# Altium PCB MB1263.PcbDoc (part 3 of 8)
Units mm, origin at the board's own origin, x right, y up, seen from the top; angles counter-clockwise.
Board outline 86 x 120 mm, 6 copper layers (Top Layer, Signal Layer 1, Signal Layer 2, Signal Layer 3, Signal Layer 4, Bottom Layer), stack 1.556 mm thick; 392 components, 421 nets, 1978 pads, 1444 vias.
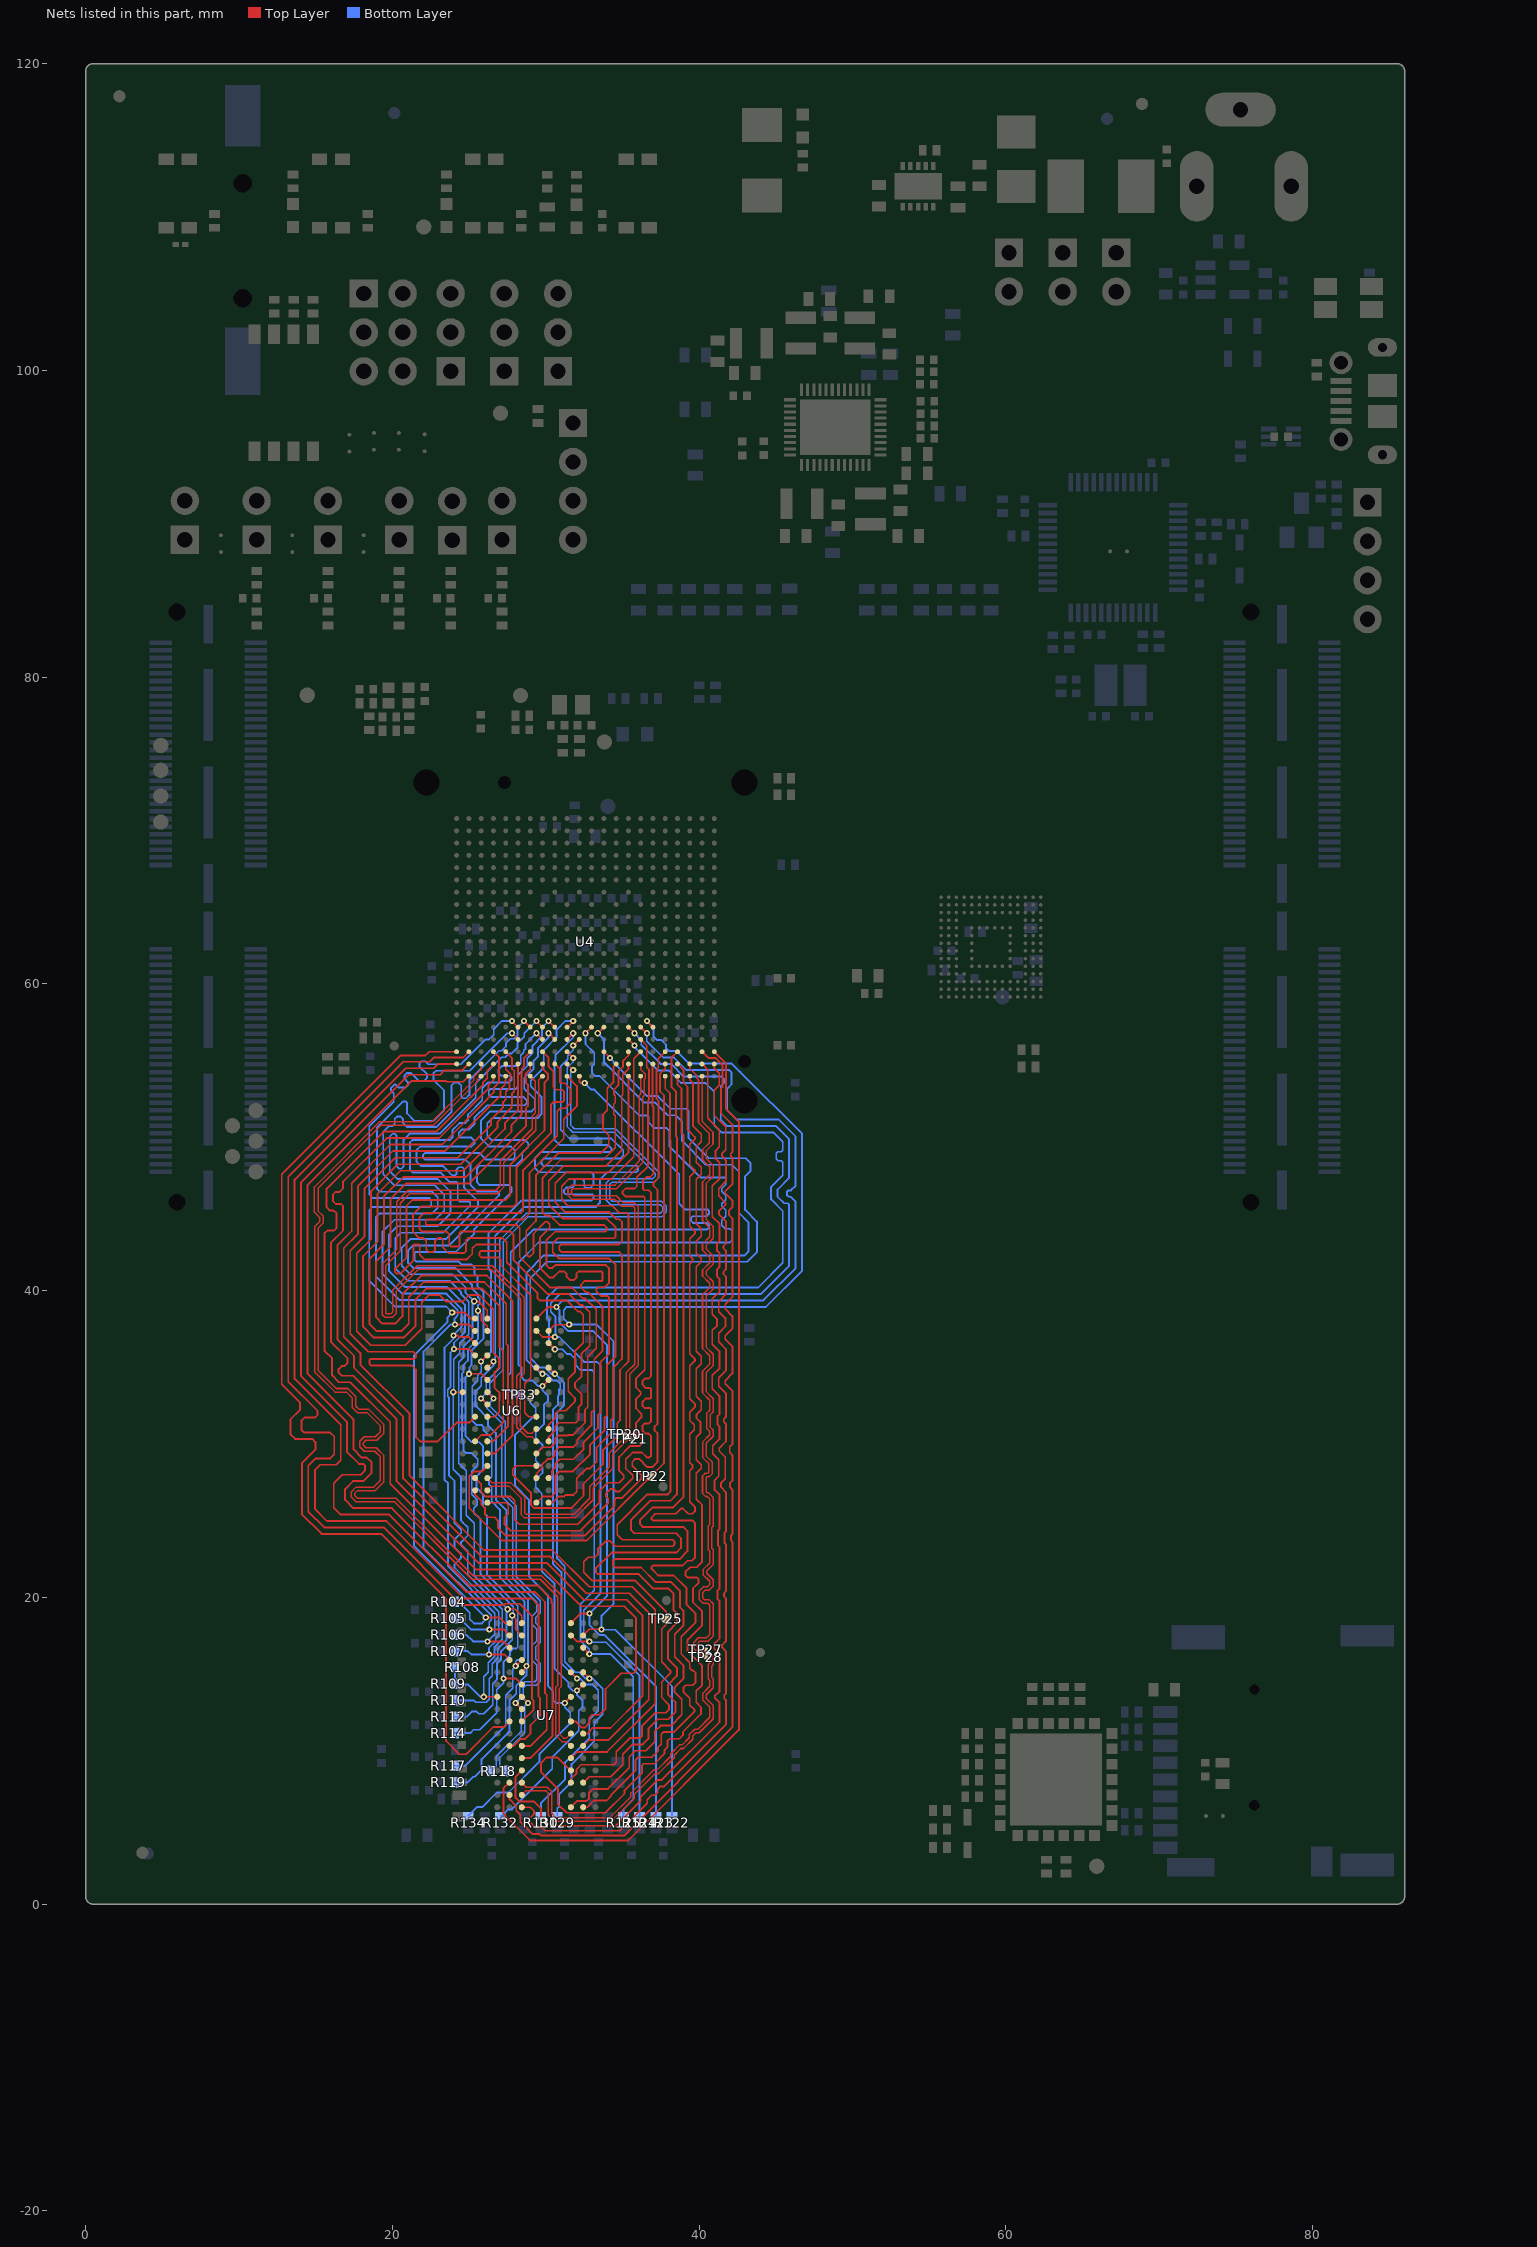
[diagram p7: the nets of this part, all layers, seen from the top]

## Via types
v1: diameter 0.4, hole 0.2, Top Layer to Bottom Layer, tented both sides, 771 vias
v2: diameter 0.6, hole 0.3, Top Layer to Bottom Layer, tented both sides, 670 vias
v3: diameter 0.4, hole 0.2, Top Layer to Bottom Layer, 3 vias

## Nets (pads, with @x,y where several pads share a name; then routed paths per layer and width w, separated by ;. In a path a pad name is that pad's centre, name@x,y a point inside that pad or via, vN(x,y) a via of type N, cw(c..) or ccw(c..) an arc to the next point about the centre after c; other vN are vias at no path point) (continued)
DDR_A4: R106.1 U4.T18 U6.P8 U7.P8 | length 67.9
  Top Layer w0.12: v1(23.99,37.08) 24.27,37.08 24.37,36.98 24.99,36.98 U6.P8@25.39,36.58 ; v1(26.21,17.13) 27.23,17.13 U7.P8@27.64,16.72 ; v1(28.59,57.58) U4.T18@28.99,57.18
  Bottom Layer w0.12: R106.1@24.09,17.57 24.82,17.57 25.26,17.13 v1(26.21,17.13) 26.68,17.6 26.68,18.98 23.63,22.03 23.63,27.44 23.39,27.68 23.39,34.221 23.4,34.231 23.4,36.292 23.99,36.882 v1(23.99,37.08) 23.97,37.08 23.98,37.09 24.5,37.61 24.5,38.828 23.52,39.807 20.653,39.807 19.35,41.11 19.35,43.83 20.14,44.62 22.778,44.62 23.38,45.222 23.38,46.258 22.768,46.87 20.12,46.87 19.41,47.58 19.41,50.37 19.76,50.72 19.98,50.72 20.154,50.894 20.154,51.196 20.309,51.351 20.535,51.351 20.69,51.196 20.69,50.95 20.98,50.66 22.874,50.66 23.845,51.631 23.845,53.375 24.03,53.56 24.31,53.56 24.49,53.38 24.49,52.64 24.59,52.54 24.802,52.54 25.02,52.758 25.02,53.707 26.952,55.638 27.128,55.638 27.41,55.92 27.41,56.142 27.688,56.42 27.939,56.42 28.15,56.631 28.15,57.14 v1(28.59,57.58)
DDR_A5: R125.1 U4.H19 U6.P2 U7.P2 | length 79.3
  Top Layer w0.12: U6.P2@30.19,36.58 v1(30.59,36.18) ; U7.P2@32.44,16.72 v1(32.84,16.32) ; U4.H19@35.39,56.38 v1(35.79,55.98)
  Bottom Layer w0.12: R125.1@35.07,5.77 35.07,6.19 35.71,6.83 35.71,14.82 34.21,16.32 v1(32.84,16.32) 32.84,16.611 32.26,17.191 32.26,19.56 32.46,19.76 33.16,20.46 33.16,34.67 33.005,34.825 32.265,34.825 31.93,35.16 31.93,35.55 31.615,35.865 31.395,35.865 31.08,36.18 v1(30.59,36.18) 30.208,36.562 30.208,38.136 30.083,38.261 30.083,39.536 30.747,40.2 43.838,40.2 45.45,41.812 45.45,45.194 44.69,45.954 44.69,46.763 45.45,47.523 45.45,48.37 45.35,48.47 45.17,48.47 45.03,48.61 45.03,48.96 45.13,49.06 45.36,49.06 45.45,49.15 45.45,49.702 44.832,50.32 41.45,50.32 40.99,50.78 40.99,52.961 40.411,53.54 38.828,53.54 38.008,54.36 37.3,54.36 35.835,55.825 v1@35.835,55.834
DDR_A6: R105.1 U4.U19 U6.R8 U7.R8 | length 68.3
  Top Layer w0.12: v1(24.09,37.8) 24.97,37.8 U6.R8@25.39,37.38 ; U6.R8@25.44,37.38 U6.R8@25.44,37.393 ; v1(26.32,17.91) 27.25,17.91 U7.R8@27.64,17.52 ; v1(27.79,56.78) U4.U19@28.19,56.38
  Bottom Layer w0.12: v1@24.054,37.805 24.054,38.18 24.26,38.386 24.26,38.728 23.601,39.387 20.479,39.387 18.93,40.936 18.93,44.791 19.179,45.04 22.604,45.04 22.96,45.396 22.96,46.084 22.594,46.45 19.19,46.45 18.99,46.65 18.99,50.626 20.69,52.326 20.884,52.326 20.96,52.25 20.96,51.55 21.43,51.08 22.7,51.08 23.37,51.75 23.37,53.05 22.68,53.74 22.68,54.17 22.85,54.34 25.059,54.34 27.499,56.78 v1(27.79,56.78) ; R105.1@24.09,18.64 24.38,18.64 25.11,17.91 v1(26.32,17.91) 26.32,18.401 26.45,18.531 26.45,18.829 22.03,23.249 22.03,36.03 23.8,37.8 v1(24.09,37.8)
DDR_A7: R122.1 U4.F18 U6.R2 U7.R2 | length 80.7
  Top Layer w0.12: U6.R2@30.19,37.38 30.59,37.78 v1@31.509,37.78 ; U7.R2@32.44,17.52 32.84,17.92 v1(33.64,17.92) ; v1(36.59,57.58) U4.F18@36.99,57.18
  Bottom Layer w0.12: v1(36.59,57.58) 37.03,57.14 37.03,56.56 37.24,56.35 37.529,56.35 37.83,56.049 37.83,55.831 38.041,55.62 38.53,55.62 39.35,54.8 42.116,54.8 42.668,54.248 42.686,54.248 46.71,50.224 46.71,41.29 44.36,38.94 31.381,38.94 31.17,38.729 31.17,38.16 v1(31.53,37.8) 33.304,37.8 34.42,36.684 34.42,19.59 33.64,18.81 v1(33.64,17.92) 33.67,17.89 34.539,17.89 38.23,14.199 R122.1@38.23,5.77
DDR_A8: R104.1 U4.U18 U6.T8 U7.T8 | length 69.6
  Top Layer w0.12: v1(23.9,38.57) 24.724,38.57 25.114,38.18 U6.T8@25.39,38.18 ; v1@26.18,18.68 27,18.68 27.36,18.32 U7.T8@27.64,18.32 ; v1(27.79,57.58) U4.U18@28.19,57.18
  Bottom Layer w0.12: R104.1@24.09,19.72 24.33,19.72 25.05,19 25.05,18.581 25.321,18.31 25.84,18.31 26.09,18.56 v1(26.09,18.68) 21.42,23.35 21.42,35.79 23.6,37.97 23.6,38.27 v1(23.9,38.57) 23.503,38.967 20.16,38.967 18.49,40.637 18.49,45.26 18.69,45.46 22.43,45.46 22.54,45.57 22.54,45.91 22.42,46.03 18.73,46.03 18.49,46.27 18.49,50.72 20.09,52.32 20.09,52.86 19.915,53.035 19.915,53.215 20.13,53.43 20.22,53.43 20.415,53.235 20.84,53.235 21.01,53.405 21.01,53.6 20.8,53.81 20.8,54.03 20.97,54.2 21.21,54.2 21.72,53.69 22.07,53.69 22.26,53.88 22.26,54.1 21.76,54.6 21.76,54.81 21.91,54.96 22.15,54.96 22.35,54.76 24.461,54.76 26.081,56.38 26.299,56.38 26.615,56.696 26.615,57.055 27.14,57.58 v1(27.79,57.58)
DDR_A9: R124.1 U4.H18 U6.R3 U7.R3 | length 81.9
  Top Layer w0.12: U6.R3@29.39,37.38 29.79,36.98 v1(30.59,36.98) ; U7.R3@31.64,17.52 32.04,17.12 v1(32.84,17.12) ; U4.H18@35.39,57.18 v1(35.79,56.78)
  Bottom Layer w0.12: v1(30.59,36.98) 30.87,36.98 32.5,35.35 33.35,35.35 33.58,35.12 33.58,20.27 32.48,19.17 32.48,17.48 v1(32.84,17.12) 32.88,17.08 33.929,17.08 36.12,14.889 R124.1@36.12,5.77 ; v1@30.633,37 30.633,38.325 30.323,38.635 30.323,39.182 30.921,39.78 44.012,39.78 45.87,41.638 45.87,45.61 45.78,45.7 45.538,45.7 45.11,46.128 45.11,46.589 45.87,47.349 45.87,49.876 45.006,50.74 41.81,50.74 41.41,51.14 41.41,53.344 41.63,53.564 41.63,53.79 41.46,53.96 39.002,53.96 38.182,54.78 37.487,54.78 36.23,56.033 36.23,56.34 v1(35.79,56.78)
DDR_A10: R114.1 U4.N18 U6.L7 U7.L7 | length 75
  Top Layer w0.12: v1(24.99,34.58) 25.79,34.58 U6.L7@26.19,34.18 ; v1(27.24,14.72) 28.04,14.72 U7.L7@28.44,14.32 ; U4.N18@31.39,57.18 v1(31.79,57.58)
  Bottom Layer w0.12: R114.1@24.09,11.15 25.071,11.15 25.291,11.37 25.69,11.37 26.81,12.49 26.81,13.98 27.24,14.41 v1(27.24,14.72) 27.24,15.788 27.68,16.228 27.68,16.469 27.891,16.68 28.089,16.68 28.177,16.768 28.177,19.463 26.174,21.466 26.174,25.32 26.04,25.454 26.04,25.819 25.9,25.959 25.9,26.74 25.49,27.15 25.49,27.91 25.9,28.32 25.9,29.89 25.67,30.12 25.17,30.12 24.77,30.52 24.77,34.36 v1(24.99,34.58) ; v1@25.033,34.58 25.033,35.01 25.153,35.13 25.153,36.093 25.95,36.89 25.95,39.892 25.549,40.293 25.549,40.891 25.35,41.09 25.35,41.53 25.16,41.72 24.48,41.72 24.293,41.907 21.8,41.907 21.797,41.91 21.52,41.91 21.45,41.98 21.45,42.46 21.51,42.52 24.146,42.52 25.333,43.707 25.333,43.993 27.78,46.44 27.78,46.72 27.62,46.88 25.71,46.88 25.53,47.06 25.53,47.078 25.52,47.088 25.52,47.98 25.68,48.14 28.04,48.14 28.47,48.57 28.47,49.002 28.86,49.392 28.86,49.62 28.66,49.82 26.48,49.82 26.19,50.11 26.19,50.914 26.526,51.25 29.466,51.25 29.72,51.504 29.72,52.64 29.02,53.34 29.02,53.69 29.865,54.535 29.865,55.681 30.69,56.506 30.69,56.989 31.281,57.58 v1(31.79,57.58)
DDR_A11: R112.1 U4.P19 U6.R7 U7.R7 | length 77.4
  Top Layer w0.12: v1@25.51,38.69 v1@25.514,38.69 ; v1(25.58,38.69) 25.81,38.46 25.81,38.051 26.19,37.671 U6.R7@26.19,37.38 ; v1(27.817,18.82) 28.06,18.577 28.06,17.9 U7.R7@28.44,17.52 ; v1(30.19,56.78) U4.P19@30.59,56.38
  Bottom Layer w0.12: R112.1@24.09,12.22 24.861,12.22 25.211,12.57 25.469,12.57 25.619,12.42 25.969,12.42 26.54,12.991 26.54,14.36 26.816,14.636 26.816,15.674 27.09,15.949 27.09,16.5 27.817,17.227 v1(27.817,18.82) 27.83,18.82 27.88,18.87 27.88,19.379 25.75,21.509 25.75,25.09 25.31,25.53 25.31,25.82 25.53,26.04 25.53,26.37 25.18,26.72 25.18,28.22 25.57,28.61 25.57,29.01 25.17,29.41 24.81,29.41 24.63,29.59 24.63,30.203 24.55,30.283 24.55,34.61 24.63,34.69 24.63,35.15 24.933,35.453 24.933,36.184 25.58,36.831 v1(25.58,38.69) 25.58,39.041 25.7,39.161 25.7,39.459 25.58,39.579 25.58,39.753 25.189,40.143 25.189,40.393 24.095,41.487 21.349,41.487 21.03,41.806 21.03,42.634 21.336,42.94 23.686,42.94 26.95,46.204 26.95,46.36 26.85,46.46 25.536,46.46 25.11,46.886 25.11,46.904 25.1,46.914 25.1,48.2 24.75,48.55 22.12,48.55 21.99,48.68 22,48.69 22,48.85 22.13,48.98 25.66,48.98 26.08,48.56 27.866,48.56 27.98,48.674 27.98,49.15 27.73,49.4 26.306,49.4 25.77,49.936 25.77,51.088 26.352,51.67 29.05,51.67 29.3,51.92 29.3,52.466 28.6,53.166 28.6,53.864 29.21,54.474 29.21,54.986 29.505,55.281 29.505,55.831 30.19,56.516 v1(30.19,56.78)
DDR_A12: R117.1 U4.N19 U6.N7 U7.N7 | length 76.3
  Top Layer w0.12: v1(25.79,35.38) U6.N7@26.19,35.78 ; v1(28.04,15.52) U7.N7@28.44,15.92 ; U4.N19@31.39,56.38 v1(31.79,56.78)
  Bottom Layer w0.12: R117.1@24.09,9.02 24.75,9.02 27.39,11.66 27.39,13.61 27.85,14.07 27.85,15.33 v1(28.04,15.52) 28.04,15.83 28.13,15.92 28.44,15.92 28.617,16.097 28.617,19.713 27.014,21.316 27.014,25.729 26.48,26.263 26.48,27.2 26.29,27.39 26.29,27.69 26.48,27.88 26.48,30.36 25.95,30.89 25.95,31.12 25.84,31.23 25.5,31.23 25.21,31.52 25.21,33.77 25.57,34.13 25.57,34.479 25.79,34.699 v1(25.79,35.38) 26.44,36.03 26.44,41.23 26.269,41.401 26.269,43.741 28.398,45.87 32.98,45.87 33.11,46 33.11,46.2 33.02,46.29 31.29,46.29 31.19,46.39 31.19,46.56 31.36,46.73 31.745,46.73 31.87,46.855 31.87,47.17 32,47.3 32.35,47.3 32.51,47.14 32.51,46.8 32.6,46.71 32.93,46.71 33.11,46.89 33.11,47.58 32.97,47.72 29.56,47.72 29.31,47.97 29.31,48.654 29.686,49.03 34.17,49.03 34.29,49.15 34.29,49.26 34.05,49.5 30.9,49.5 30.56,49.84 30.56,54.961 30.63,55.031 30.63,55.345 31.79,56.505 v1(31.79,56.78)
DDR_A13: R123.1 U4.G18 U6.T3 U7.T3 | length 82.1
  Top Layer w0.12: U6.T3@29.39,38.18 30.15,38.94 v1(30.7,38.94) ; U7.T3@31.64,18.32 32.28,18.96 v1(32.86,18.96) ; U4.G18@36.19,57.18 v1(36.59,56.78)
  Bottom Layer w0.12: v1(36.59,56.78) 36.59,56.271 37.661,55.2 38.356,55.2 39.176,54.38 41.95,54.38 42.1,54.23 42.1,53.44 41.83,53.17 41.83,51.77 42.44,51.16 45.18,51.16 46.29,50.05 46.29,46.85 45.98,46.54 45.818,46.54 45.74,46.462 45.74,46.21 45.83,46.12 45.97,46.12 46.29,45.8 46.29,41.464 44.186,39.36 31.12,39.36 v1(30.7,38.94) 30.89,38.75 30.89,37.931 31.446,37.375 33.056,37.375 34,36.431 34,20.1 v1(32.86,18.96) 32.86,18.191 33.491,17.56 33.82,17.56 37.19,14.19 R123.1@37.19,5.77
DDR_A14: R110.1 U4.P18 U6.T7 U7.T7 | length 76.2
  Top Layer w0.12: v1(25.34,39.31) 25.6,39.31 26.19,38.72 U6.T7@26.19,38.18 ; v1(27.52,19.23) 28.01,19.23 28.44,18.8 U7.T7@28.44,18.32 ; v1(30.19,57.58) U4.P18@30.59,57.18
  Bottom Layer w0.12: R110.1@24.09,13.29 25.3,13.29 25.43,13.16 26.109,13.16 26.32,13.371 26.32,14.69 26.515,14.885 26.515,15.685 26.87,16.04 26.87,16.659 27.45,17.239 27.45,19.16 v1(27.52,19.23) 25.334,21.416 25.334,24.836 24.82,25.35 24.82,28.259 24.33,28.749 24.33,35.332 24.63,35.632 24.63,36.34 25.22,36.93 25.22,39.19 v1@25.337,39.308 ; v1(25.34,39.31) v1@25.337,39.308 ; v1(30.19,57.58) 29.75,57.14 29.75,56.585 29.145,55.98 29.145,55.515 28.79,55.16 28.79,54.648 28.18,54.038 28.18,53.3 28.02,53.14 26.39,53.14 26.28,53.03 26.28,52.78 26.43,52.63 28.542,52.63 28.76,52.412 28.76,52.22 28.63,52.09 26.178,52.09 25.35,51.262 25.35,50.86 25,50.51 24.554,50.51 24.33,50.286 24.33,50.058 24.41,49.978 25.152,49.978 25.35,49.78 25.35,49.59 25.16,49.4 21.82,49.4 21.57,49.15 21.57,48.42 21.86,48.13 23.29,48.13 23.92,47.5 24.06,47.5 24.19,47.63 24.19,47.91 24.33,48.05 24.56,48.05 24.68,47.93 24.68,46.722 25.59,45.812 25.59,45.458 23.492,43.36 21.162,43.36 20.61,42.808 20.61,41.632 21.175,41.067 23.921,41.067 24.769,40.219 24.769,39.876 v1@25.337,39.308
DDR_A15: R119.1 U4.M19 U6.M7 U7.M7 | length 76.7
  Top Layer w0.12: U6.M7@26.19,34.98 v1(26.59,35.38) ; U7.M7@28.44,15.12 28.74,15.42 v1(28.74,15.52) ; v1(31.79,55.98) U4.M19@32.19,56.38
  Bottom Layer w0.12: R119.1@24.09,7.94 24.911,7.94 25.281,8.31 25.369,8.31 25.82,8.761 25.82,9.46 27.64,11.28 27.64,13.29 28.08,13.73 28.08,14.252 28.74,14.912 v1(28.74,15.52) 28.837,15.617 28.837,19.863 27.434,21.266 27.434,25.691 26.75,26.375 26.75,30.711 26.23,31.231 26.23,31.69 25.43,32.49 25.43,33.43 25.79,33.79 25.79,34.31 26.59,35.11 v1(26.59,35.38) 26.705,35.495 26.705,43.583 28.572,45.45 33.26,45.45 33.53,45.72 33.53,47.23 34.02,47.72 35.91,47.72 36.01,47.82 36.01,48.05 35.92,48.14 29.85,48.14 29.73,48.26 29.73,48.48 29.86,48.61 34.85,48.61 35.05,48.81 35.05,49.149 34.279,49.92 31.55,49.92 30.98,50.49 30.98,54.645 31.43,55.095 31.43,55.329 31.79,55.689 v1(31.79,55.98)
DDR_BA0: R129.1 U4.K20 U6.M2 U7.M2 | length 75.9
  Top Layer w0.12: U6.M2@30.19,34.98 v1(30.59,34.58) ; U7.M2@32.44,15.12 v1(32.84,14.72) ; U4.K20@33.79,55.58 v1(34.19,55.18)
  Bottom Layer w0.12: R129.1@30.75,5.77 30.75,6.24 30.87,6.36 30.87,7.166 31.685,7.981 31.685,9.135 33.16,10.61 33.16,11.83 33.72,12.39 33.72,14.04 33.04,14.72 v1(32.84,14.72) 32.59,14.72 32.19,15.12 31.931,15.12 31.24,15.811 31.24,22.04 30.74,22.54 30.74,32.063 31.18,32.503 31.18,34.01 30.61,34.58 v1(30.59,34.58) 30.351,34.58 29.941,34.99 29.62,34.99 28.99,35.62 28.99,40.819 30.051,41.88 43.142,41.88 43.77,42.508 43.77,44.498 43,45.268 43,47.449 43.34,47.789 43.34,48.33 43.04,48.63 40.618,48.63 39.31,49.938 39.31,51.706 39.156,51.86 38.132,51.86 37.312,52.68 36.604,52.68 34.42,54.864 34.42,54.94 34.185,55.175 v1@34.18,55.18
DDR_BA1: R107.1 U4.R18 U6.N8 U7.N8 | length 70.2
  Top Layer w0.12: v1@24.029,36.2 24.97,36.2 U6.N8@25.39,35.78 ; v1(26.29,16.28) 27.28,16.28 U7.N8@27.64,15.92 ; v1(29.39,57.58) U4.R18@29.79,57.18
  Bottom Layer w0.12: 24.064,23.792 24.486,24.214 24.486,24.4 24.05,24.836 24.05,27.61 23.689,27.971 23.689,33.041 23.61,33.12 23.61,33.529 23.78,33.699 23.78,35.96 v1(24.02,36.2) 24.02,36.601 24.74,37.321 24.74,38.927 24.74,39.06 23.573,40.227 20.827,40.227 19.77,41.284 19.77,43.654 20.316,44.2 22.952,44.2 23.8,45.048 23.8,46.432 22.942,47.29 20.32,47.29 19.83,47.78 19.83,50.05 20.01,50.23 20.15,50.23 20.28,50.1 20.28,48.11 20.44,47.95 20.585,47.95 20.73,48.095 20.73,49.85 21.12,50.24 23.096,50.24 25.44,52.584 25.44,53.533 27.126,55.218 27.362,55.218 27.609,55.465 27.785,55.465 28.15,55.831 28.15,56.122 28.594,56.565 28.594,56.784 v1(29.39,57.58) ; 24.068,23.788 24.05,23.77 24.05,23.28 24.47,22.86 24.47,22.566 24.05,22.146 24.05,21.95 26.94,19.06 26.94,17.549 26.74,17.349 26.74,17.151 26.29,16.701 v1(26.29,16.28) 25.14,16.28 24.92,16.5 R107.1@24.09,16.5
DDR_BA2: R130.1 U4.K18 U6.M3 U7.M3 | length 77.1
  Top Layer w0.12: U6.M3@29.39,34.98 v1@29.77,34.6 ; U7.M3@31.64,15.12 v1(32.04,14.72) ; v1(33.39,56.78) U4.K18@33.79,57.18
  Bottom Layer w0.12: R130.1@29.68,5.77 29.68,6.57 31.265,8.155 31.265,9.255 32.84,10.83 32.84,12.02 33.42,12.6 33.42,13.94 33.03,14.33 32.62,14.33 32.23,14.72 v1(32.04,14.72) 32.02,14.72 31.02,15.72 31.02,21.65 30.467,22.203 30.467,32.243 30.63,32.405 ; 30.63,32.406 30.79,32.566 30.79,33.117 30.86,33.187 ; 30.87,33.187 30.87,33.551 30.95,33.631 30.95,33.929 30.739,34.14 30.48,34.14 30.04,34.58 v1(29.79,34.58) 29.719,34.58 29.354,34.944 29.276,34.944 28.748,35.472 28.748,41.17 29.877,42.3 42.968,42.3 43.21,42.542 43.21,44.464 42.58,45.094 42.58,47.77 42.14,48.21 40.444,48.21 38.89,49.764 38.89,51.02 38.47,51.44 37.958,51.44 37.138,52.26 36.43,52.26 33.835,54.855 ; v1(33.39,56.78) 33.79,56.38 33.79,54.9 34.08,54.61
DDR_CASN: R134.1 TP33.1 U4.M22 U6.K3 U7.K3 | length 75.4
  Top Layer w0.12: v1(28.99,32.98) U6.K3@29.39,33.38 ; v1(31.24,13.12) U7.K3@31.64,13.52 ; U4.M22@32.19,53.98 32.19,53.62 32.28,53.53 v1(32.54,53.53)
  Bottom Layer w0.12: R134.1@24.94,5.77 25.5,6.33 25.86,6.33 26.81,7.28 27.57,7.28 29.585,9.295 29.585,9.775 29.84,10.03 31.6,11.79 31.6,12.469 31.24,12.829 v1(31.24,13.12) 30.64,13.12 30.47,13.29 30.47,13.9 30.14,14.23 30.14,20.14 28.904,21.376 28.904,26.363 28,27.267 28,30.596 29.35,31.946 29.35,32.329 28.99,32.689 v1(28.99,32.98) 28.27,32.98 TP33.1@28.179,32.98 ; TP33.1@28.27,33.22 28.27,33.071 TP33.1@28.179,32.98 ; v1(32.54,53.53) 32.962,53.108 33.17,53.108 38.7,47.578 38.7,45.656 39.056,45.3 40.55,45.3 40.64,45.21 40.64,45 40.49,44.85 39.59,44.85 39.46,44.72 39.46,44.57 39.61,44.42 40.51,44.42 40.64,44.29 40.64,44.11 40.51,43.98 29.181,43.98 27.719,42.518 27.719,34.653 27.533,34.466 27.533,33.627 28.105,33.055 TP33.1@28.179,32.98
DDR_CKE: R108.2 R109.1 U4.R19 U6.K9 U7.K9 | length 69.4
  Top Layer w0.12: v1(23.97,33.38) U6.K9@24.59,33.38 ; v1(25.96,13.52) U7.K9@26.84,13.52 ; v1(29.39,56.78) U4.R19@29.79,56.38
  Bottom Layer w0.12: R108.2@24.09,15.44 R109.1@24.09,14.37 24.14,14.32 24.935,14.32 25.735,13.52 v1(25.96,13.52) 25.96,14.82 26.25,15.11 26.25,15.73 26.65,16.131 26.65,16.75 27.16,17.26 27.16,19.214 24.91,21.464 24.91,23.014 24.484,23.44 24.484,23.61 24.91,24.036 24.91,24.574 24.604,24.88 24.6,24.88 24.48,25 24.48,27.84 23.97,28.35 v1(23.97,33.38) 24,33.41 24,35.54 24.389,35.929 24.389,36.569 24.98,37.16 24.98,38.939 ; 24.98,38.78 24.98,39.289 24.469,39.8 24.469,39.925 23.747,40.647 21.001,40.647 20.19,41.458 20.19,43.41 20.56,43.78 23.3,43.78 25.073,45.553 25.073,45.735 24.992,45.816 24.384,45.816 24.26,45.94 24.26,47.01 24.19,47.08 23.746,47.08 23.116,47.71 21.32,47.71 21.15,47.88 21.15,49.66 21.31,49.82 23.74,49.82 23.91,49.99 23.91,50.46 24.38,50.93 24.76,50.93 24.93,51.1 24.93,51.48 25.86,52.41 25.86,53.204 26.216,53.56 27.6,53.56 27.76,53.72 27.76,53.92 27.67,54.01 27.11,54.01 26.9,54.22 26.9,54.399 27.152,54.651 28.199,54.651 28.37,54.822 28.37,55.334 28.57,55.534 28.57,55.66 28.69,55.78 28.69,56.08 v1(29.39,56.78)
DDR_CLK_N: R118.2 U4.N21 U6.K7 U7.K7 | length 71.6
  Top Layer w0.1: U6.K7@26.19,33.38 v1(26.59,32.98) ; U7.K7@28.44,13.52 v1(28.84,13.12) ; U4.N21@31.39,54.78 v1(31.79,54.38)
  Bottom Layer w0.1: v1(26.59,32.98) 26.59,32.93 26.35,32.69 26.35,32.475 27.37,31.455 27.37,26.66 28.074,25.956 28.074,21.341 29.64,19.775 29.64,18.985 29.36,18.705 29.36,18.32 29.64,18.04 29.64,17.065 29.34,16.765 29.34,15.995 29.65,15.685 29.65,14.54 29.38,14.27 28.72,14.27 28.54,14.09 28.54,13.42 v1(28.84,13.12) 28.62,12.9 28.62,11.165 27.01,9.555 27.01,9.01 R118.2@27.34,8.68 ; v1@26.633,33 26.621,33.011 26.35,33.283 26.35,33.965 27.24,34.855 27.24,43.213 28.837,44.81 37.555,44.81 37.87,45.125 37.87,45.515 37.555,45.83 34.33,45.83 34.17,45.99 34.17,46.93 34.32,47.08 37.075,47.08 37.38,47.385 37.38,47.724 34.544,50.56 31.86,50.56 31.62,50.8 31.62,54.21 v1(31.79,54.38)
DDR_CLK_P: R118.1 U4.N20 U6.J7 U7.J7 | length 72.5
  Top Layer w0.1: v1(25.79,32.98) U6.J7@26.19,32.58 ; v1(28.04,13.12) U7.J7@28.44,12.72 ; U4.N20@31.39,55.58 v1(31.79,55.18)
  Bottom Layer w0.1: v1(25.79,32.98) 26.12,32.65 26.12,32.38 27.14,31.36 27.14,26.565 27.844,25.861 27.844,21.246 29.41,19.68 29.41,19.08 29.13,18.8 29.13,18.225 29.41,17.945 29.41,17.16 29.11,16.86 29.11,15.9 29.42,15.59 29.42,14.635 29.285,14.5 28.625,14.5 28.31,14.185 28.31,13.39 v1(28.04,13.12) 28.39,12.77 28.39,11.26 26.78,9.65 26.78,9.02 R118.1@26.44,8.68 ; v1@25.833,33.025 26.12,33.313 26.12,34.06 27.01,34.95 27.01,43.308 28.742,45.04 37.46,45.04 37.64,45.22 37.64,45.42 37.46,45.6 34.235,45.6 33.94,45.895 33.94,47.025 34.225,47.31 36.98,47.31 37.15,47.48 37.15,47.629 34.449,50.33 31.765,50.33 31.39,50.705 31.39,54.517 31.78,54.907 31.78,55.17 v1(31.79,55.18)
DDR_CSN: R132.1 U4.L18 U6.L2 U7.L2 | length 78.7
  Top Layer w0.12: v1(29.79,33.78) U6.L2@30.19,34.18 ; v1(32.04,13.92) U7.L2@32.44,14.32 ; v1(32.59,56.78) U4.L18@32.99,57.18
  Bottom Layer w0.12: R132.1@27.04,5.77 27.15,5.77 27.56,6.18 27.79,6.18 30.425,8.815 30.425,9.565 32.155,11.295 32.155,12.605 32.4,12.85 32.4,13.269 32.04,13.629 v1(32.04,13.92) 31.749,13.92 31.47,14.2 31.47,14.47 30.58,15.36 30.58,20.88 29.744,21.716 29.744,26.776 29.35,27.17 29.35,27.68 29.78,28.11 29.78,28.49 29.35,28.92 29.35,29.346 29.78,29.776 29.78,29.96 29.35,30.39 29.35,30.758 29.884,31.292 29.884,32.565 30.15,32.831 30.15,33.129 30.003,33.276 29.79,33.489 v1(29.79,33.78) 29.499,33.78 29.139,34.14 28.64,34.14 28.426,34.354 28.426,34.966 28.219,35.174 28.219,41.83 29.529,43.14 42,43.14 42.161,43.301 42.161,43.889 42.01,44.04 41.71,44.04 41.48,44.27 41.48,44.58 41.74,44.84 41.74,45.26 41.48,45.52 41.48,45.67 41.74,45.93 41.74,46.22 41.48,46.48 41.48,46.66 41.74,46.92 41.74,47.28 41.65,47.37 40.096,47.37 38.05,49.416 38.05,50.43 37.88,50.6 37.066,50.6 36.7,50.966 36.7,51.34 36.62,51.42 36.082,51.42 33.507,53.995 33.216,53.995 33.005,54.206 33.005,54.605 33.16,54.76 33.16,55.51 32.59,56.08 v1(32.59,56.78)
DDR_DQ0: TP22.1 U4.E21 U6.D7 | length 45.5
  Top Layer w0.12: U6.D7@26.19,28.58 26.19,28.557 25.834,28.202 25.303,28.202 25.01,27.909 25.01,25.831 27.131,23.71 32.67,23.71 TP22.1@36.85,27.89 37.71,28.75 37.71,52.735 37.45,52.995 37.45,54.13 37.79,54.47 U4.E21@37.79,54.78
DDR_DQ1: U4.F21 U6.A7 | length 45.6
  Top Layer w0.12: U6.A7@26.19,26.17 27.43,26.17 27.56,26.04 27.56,25.44 27.3,25.18 27.3,24.76 27.71,24.35 32.259,24.35 34.07,26.161 34.07,26.42 33.931,26.559 33.931,26.788 34.204,27.06 34.45,27.06 34.56,26.95 34.56,26.94 34.59,26.91 34.819,26.91 35.67,27.761 35.67,27.957 35.221,28.406 35.221,29.004 35.664,29.447 36.277,29.447 36.594,29.13 36.76,29.13 36.87,29.24 36.87,30.52 36.71,30.68 36.49,30.68 36.31,30.86 36.31,31.21 36.43,31.33 36.7,31.33 36.87,31.5 36.87,32.27 36.78,32.36 36.44,32.36 36.31,32.49 36.31,32.77 36.51,32.97 36.82,32.97 36.87,33.02 36.87,33.58 36.8,33.65 36.52,33.65 36.31,33.86 36.31,34.12 36.455,34.265 36.7,34.265 36.87,34.435 36.87,46.39 36.71,46.55 36.416,46.55 36.35,46.616 36.35,47.206 36.554,47.41 36.8,47.41 37.03,47.64 37.03,51.98 36.97,52.04 36.97,54.76 U4.F21@36.99,54.78
DDR_DQ2: U4.H21 U6.A3 | length 46.3
  Top Layer w0.12: U6.A3@29.39,26.18 29.79,26.58 30.392,26.58 30.63,26.818 30.63,27.929 30.921,28.22 31.77,28.22 32.889,29.339 32.889,29.939 33.82,30.87 33.82,31.71 34,31.89 34,35.176 34.55,35.726 34.55,36.353 34.55,41.68 34.14,42.09 30.886,42.09 30.46,42.516 30.46,43.104 30.776,43.42 34.47,43.42 34.55,43.5 34.55,44.127 33.977,44.7 31.097,44.7 30.2,45.597 30.2,47.162 31.168,48.13 33.938,48.13 34.95,49.142 34.95,52.72 35.025,52.795 35.025,54.068 35.39,54.433 U4.H21@35.39,54.78
DDR_DQ3: U4.E20 U6.B8 | length 45.5
  Top Layer w0.12: U6.B8@25.39,26.98 25.39,26.7 25.8,26.29 25.8,26.061 26.041,25.82 26.041,25.394 26.207,25.227 26.663,25.227 26.88,25.01 26.88,24.555 27.405,24.03 32.533,24.03 34.49,25.987 34.49,26.37 34.61,26.49 34.993,26.49 36.23,27.727 36.23,27.991 35.641,28.58 35.641,28.83 35.838,29.027 36.103,29.027 36.63,28.5 36.935,28.5 37.29,28.855 37.29,30.694 37.08,30.904 37.08,31.116 37.29,31.326 37.29,46.564 37.03,46.824 37.03,47.046 37.35,47.366 37.35,52.37 37.21,52.51 37.21,54.375 37.34,54.505 37.34,55.13 U4.E20@37.79,55.58
DDR_DQ4: U4.J21 U6.C3 | length 46.3
  Top Layer w0.12: U6.C3@29.39,27.78 29.39,28.071 29.53,28.211 29.53,28.22 29.539,28.22 29.75,28.431 29.75,28.649 30.121,29.02 30.339,29.02 30.575,29.256 30.575,29.505 30.875,29.805 31.803,29.805 32.049,30.051 32.049,30.287 32.98,31.218 32.98,32.058 33.16,32.238 33.16,35.524 33.71,36.074 33.71,38.951 32.761,39.9 32.604,39.9 32.3,40.204 32.3,40.39 32.55,40.64 33.66,40.64 33.71,40.69 33.71,41.19 33.65,41.25 32.13,41.25 32,41.12 32,40.85 31.85,40.7 31.57,40.7 31.36,40.91 31.36,41.1 31.21,41.25 30.889,41.25 30.499,40.86 30.239,40.86 29.62,41.479 29.62,43.452 30.26,44.092 30.26,44.32 30.09,44.49 29.975,44.49 29.2,43.715 29.2,42.45 28.969,42.219 28.879,42.219 28.73,42.369 28.73,43.91 29.36,44.54 29.36,47.51 30.82,48.97 33.59,48.97 34.11,49.49 34.11,50.136 33.74,50.506 33.74,51.495 34.015,51.77 34.015,53.186 34.41,53.581 34.41,54.6 U4.J21@34.59,54.78
DDR_DQ5: U4.H20 U6.C2 | length 46.5
  Top Layer w0.12: U6.C2@30.19,27.78 30.41,28 30.41,28.26 30.625,28.475 30.63,28.475 30.63,28.729 30.911,29.01 31.808,29.01 32.469,29.671 32.469,30.113 33.4,31.044 33.4,31.884 33.58,32.064 33.58,35.35 34.13,35.9 34.13,36.527 34.13,39.53 33.998,39.662 33.592,39.662 33.29,39.965 33.29,40.08 33.43,40.22 33.834,40.22 34.13,40.516 34.13,41.46 33.92,41.67 30.626,41.67 30.437,41.481 30.211,41.481 30.04,41.653 30.04,43.278 30.602,43.84 33.88,43.84 33.983,43.943 33.983,44.1 33.803,44.28 30.9,44.28 30.27,44.91 29.975,44.91 29.785,45.1 29.78,45.1 29.78,47.336 30.994,48.55 33.764,48.55 34.53,49.316 34.53,51.41 34.435,51.505 34.435,52.17 34.53,52.265 34.53,52.719 34.45,52.799 34.45,53.112 34.73,53.392 ; 34.74,53.392 34.74,54.292 35.03,54.582 35.03,54.97 35.39,55.33 U4.H20@35.39,55.58
DDR_DQ6: U4.H22 U6.A2 | length 45.6
  Top Layer w0.12: U6.A2@30.19,26.18 30.44,26.18 30.85,26.59 31.2,26.59 31.29,26.68 31.81,26.68 32.024,26.894 32.024,27.774 32.65,28.4 32.871,28.4 33.309,28.838 33.309,29.765 34.24,30.696 34.24,31.536 34.42,31.716 34.42,35.002 34.97,35.552 34.97,42.34 34.8,42.51 31.03,42.51 30.88,42.66 30.88,42.9 30.98,43 34.77,43 34.97,43.2 34.97,44.49 34.8,44.66 34.611,44.66 34.151,45.12 31.271,45.12 30.62,45.771 30.62,46.988 31.342,47.71 34.112,47.71 35.39,48.988 U4.H22@35.39,53.98
DDR_DQ7: U4.G19 U6.C8 | length 46.9
  Top Layer w0.12: U6.C8@25.39,27.78 25.79,27.38 25.79,26.85 26.05,26.59 27.695,26.59 27.98,26.305 27.98,25.05 28.26,24.77 32.085,24.77 33.511,26.197 33.511,26.962 34.03,27.48 34.795,27.48 35.082,27.768 35.082,27.951 34.779,28.254 34.779,29.156 35.49,29.867 36.09,29.867 36.316,30.093 36.316,30.26 35.89,30.686 35.89,31.384 36.24,31.734 36.24,31.966 35.89,32.316 35.89,32.944 36.19,33.244 36.19,33.386 35.89,33.686 35.89,34.294 36.45,34.854 36.45,46.06 36.38,46.13 35.22,46.13 35,46.35 35,46.46 35.201,46.66 35.8,46.66 35.93,46.79 35.93,47.38 36.67,48.12 36.67,52.385 36.73,52.445 36.73,54.42 36.587,54.563 36.587,55.983 U4.G19@36.19,56.38
DDR_DQ8: U4.N22 U6.E3 | length 44.1
  Top Layer w0.12: U6.E3@29.39,29.38 29.8,29.79 30.324,29.79 30.63,30.096 30.63,30.39 30.8,30.56 31.455,30.56 31.48,30.585 31.753,30.585 32.56,31.392 32.56,32.232 32.74,32.412 32.74,35.698 33.29,36.248 33.29,38.777 32.587,39.48 32.43,39.48 31.71,40.2 30.305,40.2 28.31,42.195 28.31,44.084 28.124,44.27 22.24,44.27 22.18,44.33 22.18,44.59 22.24,44.65 28.56,44.65 28.94,45.03 28.94,47.684 31.175,49.919 31.175,51.175 32.03,52.03 32.03,53.34 U4.N22@31.39,53.98
DDR_DQ9: U4.R21 U6.H3 | length 46.3
  Top Layer w0.12: U6.H3@29.39,31.78 28.881,31.78 28.63,32.031 28.63,33.929 29.019,34.318 29.019,39.704 27.05,41.673 27.05,42.02 26.9,42.17 25.79,42.17 25.68,42.28 25.68,42.49 25.78,42.59 26.94,42.59 27.03,42.68 27.03,42.9 26.92,43.01 25.47,43.01 25.21,42.75 25.21,42.39 24.855,42.035 22.085,42.035 21.79,42.33 21.79,42.95 21.73,43.01 21.42,43.01 21.37,42.96 21.37,41.96 20.52,41.11 20.29,41.11 20.17,41.23 20.17,41.39 20.92,42.14 20.92,45.535 21.295,45.91 27.38,45.91 27.68,46.21 27.68,48.206 29.915,50.441 29.915,53.555 30.14,53.78 30.14,54.139 29.939,54.34 29.93,54.34 29.79,54.48 U4.R21@29.79,54.78
DDR_DQ10: U4.P21 U6.F2 | length 45.9
  Top Layer w0.12: U6.F2@30.19,30.18 30.19,30.456 30.62,30.886 30.62,31.15 30.86,31.39 31.964,31.39 32.14,31.566 32.14,32.406 32.32,32.586 32.32,33.27 31.9,33.69 31.9,33.98 32.32,34.4 32.32,35.872 32.87,36.422 32.87,38.603 32.413,39.06 32.256,39.06 31.536,39.78 30.131,39.78 27.89,42.021 27.89,43.68 27.72,43.85 24.46,43.85 24.37,43.76 24.37,42.94 24.305,42.875 23.835,42.875 23.71,43 23.71,43.68 23.54,43.85 21.94,43.85 21.76,44.03 21.76,44.764 22.066,45.07 28.386,45.07 28.52,45.204 28.52,47.858 30.755,50.093 30.755,51.705 30.94,51.89 31.28,51.89 31.61,52.22 31.61,53.166 31.254,53.522 30.988,53.522 30.92,53.59 30.92,54.476 U4.P21@30.61,54.786
DDR_DQ11: U4.T20 U6.F7 | length 46.3
  Top Layer w0.12: U6.F7@26.19,30.18 26.58,30.18 27.55,31.15 27.55,36.41 27.42,36.54 27.42,39.141 25.996,40.565 22.054,40.565 21.07,39.581 21.07,37.85 20.58,37.36 18.974,37.36 18.515,37.819 18.515,42.084 19.45,43.019 19.45,46.144 20.706,47.4 24.795,47.4 27.77,50.375 27.77,50.82 28.43,51.48 28.43,54.212 28.463,54.244 28.463,54.503 28.59,54.63 28.59,55.18 U4.T20@28.99,55.58
DDR_DQ12: U4.V20 U6.H7 | length 45.6
  Top Layer w0.12: U6.H7@26.19,31.78 26.67,31.78 26.97,32.08 26.97,32.828 26.993,32.851 26.993,33.337 26.81,33.52 ; 26.81,33.51 26.81,33.52 ; U4.V20@27.39,55.58 27.79,55.18 27.79,54.48 27.95,54.32 27.95,53.01 27.81,52.87 27.81,52.175 27.76,52.125 27.76,51.914 26.858,51.012 26.858,50.651 24.447,48.24 20.358,48.24 18.61,46.492 18.61,43.367 17.675,42.432 17.675,37.357 18.592,36.44 20.848,36.44 21.92,37.512 21.92,39.06 21.92,39.243 22.402,39.725 23.07,39.725 23.495,39.3 24.605,39.3 25.03,39.725 25.648,39.725 26.575,38.798 26.575,35.955 26.95,35.58 26.95,34.98 26.66,34.69 26.66,33.67 26.81,33.52
DDR_DQ13: U4.R20 U6.G2 | length 46.8
  Top Layer w0.12: U4.R20@29.79,55.58 30.19,55.18 30.19,54.612 30.5,54.302 30.5,54.108 30.5,53.28 30.68,53.1 31.078,53.1 31.08,53.102 31.19,52.992 31.19,52.394 31.106,52.31 30.525,52.31 30.335,52.12 30.335,50.267 28.1,48.032 28.1,45.68 27.91,45.49 21.892,45.49 21.34,44.938 21.34,43.856 21.766,43.43 22.03,43.43 22.21,43.25 22.21,42.69 22.39,42.51 22.63,42.51 22.79,42.67 22.79,43.24 22.98,43.43 23.19,43.43 23.29,43.33 23.29,42.826 23.661,42.455 24.681,42.455 24.79,42.564 24.79,43.28 24.94,43.43 27.19,43.43 27.46,43.16 27.46,41.857 29.46,39.857 29.46,39.51 29.61,39.36 31.362,39.36 32.082,38.64 32.239,38.64 32.45,38.429 32.45,36.596 31.9,36.046 31.9,34.682 31.468,34.25 31.468,33.432 31.9,33 31.9,32.76 31.31,32.17 30.84,32.17 30.63,31.96 30.63,31.69 30.19,31.25 U6.G2@30.19,30.98
DDR_DQ14: U4.U21 U6.F8 | length 45.7
  Top Layer w0.12: U6.F8@25.39,30.18 25.81,30.6 26.41,30.6 27.23,31.42 27.23,36.09 26.995,36.325 26.995,38.972 25.822,40.145 22.228,40.145 21.5,39.417 21.5,37.686 20.754,36.94 18.8,36.94 18.095,37.645 18.095,42.258 19.03,43.193 19.03,46.318 20.532,47.82 24.621,47.82 27.34,50.539 27.34,50.9 28.19,51.75 U4.U21@28.19,54.78
DDR_DQ15: U4.V21 U6.H8 | length 45.1
  Top Layer w0.12: U6.H8@25.39,31.78 25.01,31.4 24.19,31.4 22.96,30.17 21.8,30.17 21.54,30.43 21.54,34.85 21.28,35.11 18.63,35.11 18.5,35.24 18.5,35.47 18.572,35.542 21.427,35.542 21.54,35.655 21.54,35.83 21.35,36.02 18.418,36.02 17.255,37.183 17.255,42.606 18.19,43.541 18.19,46.666 20.184,48.66 24.273,48.66 26.438,50.825 26.438,51.186 27.216,51.964 27.216,52.292 27.39,52.466 27.39,52.959 27.63,53.199 27.63,53.767 27.71,53.847 27.71,54.113 27.523,54.3 27.52,54.3 27.39,54.43 U4.V21@27.39,54.78
DDR_DQ16: U4.B21 U7.D7 | length 65.9
  Top Layer w0.12: U7.D7@28.44,8.72 28.03,8.31 28.03,6.93 28.26,6.7 29.21,6.7 29.7,6.21 29.7,5.72 30.31,5.11 34.562,5.11 36.195,6.743 36.195,6.991 37.304,8.1 37.552,8.1 41.33,11.878 41.33,13.13 41.327,13.133 ; U4.B21@40.19,54.78 40.565,54.405 40.565,51.251 ; 40.6,51.216 41.315,50.501 41.315,49.37 41.074,49.13 41.074,48.586 41.33,48.33 41.33,47.295 40.86,46.825 40.86,44.825 41.33,44.355 41.33,43.245 41.169,43.085 41.169,42.596 41.33,42.435 41.33,41.56 41.17,41.4 41.17,40.91 41.33,40.75 41.33,39.935 40.86,39.465 40.86,38.462 41.176,38.146 41.176,37.724 40.86,37.408 40.86,36.492 41.33,36.022 41.33,34.951 40.86,34.481 40.86,33.595 41.33,33.125 41.33,31.941 41.19,31.801 41.19,31.28 41.33,31.14 41.33,30.34 40.887,29.897 40.887,29.373 41.28,28.98 41.28,27.915 41.009,27.644 41.009,27.006 41.33,26.685 41.33,24.474 41.24,24.384 41.24,23.375 41.33,23.285 41.33,20.575 41.205,20.449 41.205,19.885 41.33,19.76 41.33,17.32 40.99,16.98 40.99,16.655 41.33,16.315 41.33,13.894 41.02,13.584 41.02,13.446 41.33,13.136
DDR_DQ17: U4.D21 U7.A2 | length 66.9
  Top Layer w0.12: U7.A2@32.44,6.32 32.701,6.32 33.141,6.76 33.965,6.76 34.266,7.061 34.266,7.141 35.86,8.735 35.86,9.42 36.02,9.58 36.916,9.58 37.32,9.984 37.32,10.22 37.529,10.429 37.529,11.089 37.66,11.22 38.345,11.22 39.703,12.578 39.703,12.668 39.39,12.981 39.39,13.428 38.979,13.839 38.979,14.121 39.134,14.276 39.59,14.276 39.77,14.456 39.77,15.08 39.62,15.23 39.54,15.23 39.39,15.38 39.39,15.751 38.83,16.311 38.83,17.428 39.77,18.368 39.77,18.928 39.18,19.518 39.18,20.588 38.338,21.43 37.326,21.43 36.898,21.858 36.898,21.988 36.99,22.08 38.932,22.08 39.241,22.389 39.529,22.389 39.72,22.58 39.72,24.86 39.559,25.021 36.98,25.021 36.901,25.1 36.901,25.209 37.142,25.45 38.472,25.45 38.812,25.79 38.95,25.79 39.29,25.45 39.56,25.45 39.72,25.61 39.72,25.9 39.39,26.23 39.39,26.556 39.39,27.89 39.39,28.264 39.578,28.452 39.578,28.603 39.39,28.791 39.39,30.63 39.68,30.92 39.68,31.246 39.39,31.536 39.39,32.08 39.72,32.41 39.72,32.62 39.39,32.95 39.39,35.09 39.72,35.42 39.72,35.553 39.39,35.883 39.39,41.724 39.566,41.9 39.566,42.1 39.39,42.276 39.39,43.384 39.72,43.714 39.72,43.86 39.39,44.19 39.39,47.05 39.39,47.434 39.72,47.764 39.72,47.861 39.39,48.191 39.39,49.539 39.72,49.869 39.72,50.017 39.25,50.487 39.25,51.86 39.25,53.09 39.25,53.279 38.99,53.539 38.99,54.38 U4.D21@38.59,54.78
DDR_DQ18: U4.D22 U7.A3 | length 66.2
  Top Layer w0.12: U7.A3@31.64,6.32 32.05,6.73 32.66,6.73 32.83,6.9 32.83,7.27 33.08,7.52 34.051,7.52 35.44,8.909 35.44,9.594 35.846,10 36.506,10 37.109,10.603 37.109,11.263 37.486,11.64 38.171,11.64 38.87,12.339 38.87,13.354 38.4,13.824 38.4,14.136 38.97,14.706 38.97,15.577 38.41,16.137 38.41,17.602 38.97,18.162 38.97,19.134 38.76,19.344 38.76,20.414 38.164,21.01 37.152,21.01 36.212,21.95 34.5,21.95 34.38,22.07 34.38,22.38 34.5,22.5 38.728,22.5 39.239,23.011 39.239,24.331 38.969,24.601 36.318,24.601 36.149,24.77 36.149,25.051 36.969,25.871 38.299,25.871 38.97,26.542 38.97,50.17 ; U4.D22@38.59,53.98 38.59,53.43 38.86,53.16 38.86,50.28 38.97,50.17 ; 38.97,50.173 38.97,50.17
DDR_DQ19: U4.B20 U7.B8 | length 66.6
  Top Layer w0.12: U7.B8@27.64,7.12 27.64,6.829 28.08,6.389 28.08,6.08 28.34,5.82 28.34,5.385 29.155,4.57 29.59,4.57 ; 29.596,4.57 29.59,4.57 ; U4.B20@40.19,55.58 40.6,55.17 41.053,55.17 41.53,54.693 41.53,53.29 41.42,53.18 41.42,51.584 42.17,50.834 42.17,49.037 42.059,48.926 42.059,48.789 42.17,48.678 42.17,46.947 41.7,46.477 41.7,46.354 42.17,45.884 42.17,45.45 41.957,45.237 41.957,44.916 42.17,44.703 42.17,39.587 41.7,39.117 41.7,38.81 42.17,38.34 42.17,37.53 41.7,37.06 41.7,36.84 42.17,36.37 42.17,34.603 41.7,34.133 41.7,33.943 42.17,33.473 42.17,29.992 41.994,29.816 41.994,29.454 42.17,29.278 42.17,27.617 42.022,27.468 42.022,27.182 42.17,27.033 42.17,24.126 42.08,24.036 42.08,23.723 42.17,23.633 42.17,11.53 35.11,4.47 29.69,4.47 29.59,4.57
DDR_DQ20: U4.A20 U7.C8 | length 66.2
  Top Layer w0.12: U7.C8@27.64,7.92 27.61,7.92 27.24,7.55 27.24,5.891 28.981,4.15 35.384,4.15 42.592,11.358 42.592,29.718 42.59,29.72 42.59,51.01 41.75,51.85 41.75,54.82 U4.A20@40.99,55.58
DDR_DQ21: TP25.1 U4.E22 U7.C3 | length 66.9
  Top Layer w0.12: U7.C3@31.64,7.92 31.64,8.16 32.01,8.53 32.01,8.8 32.3,9.09 34.433,9.09 34.6,9.257 34.6,9.942 35.498,10.84 36.158,10.84 36.269,10.951 36.269,11.611 37.138,12.48 37.823,12.48 38.03,12.687 38.03,13.006 37.56,13.476 37.56,14.484 38.13,15.054 38.13,15.229 37.56,15.799 37.56,17.94 37.86,18.24 37.86,18.6 37.86,19.056 35.806,21.11 32.996,21.11 32.48,21.626 32.48,22.32 32.774,22.614 33.21,22.614 33.4,22.804 33.4,23.16 33.91,23.67 34.2,23.67 34.53,23.34 38.27,23.34 38.399,23.469 38.399,23.641 38.28,23.76 35,23.76 34.66,24.1 34.66,24.75 36.63,26.72 37.96,26.72 38.13,26.89 38.13,48.756 38.13,49.825 ; U4.E22@37.79,53.98 37.79,53.18 38.1,52.87 38.1,49.855
DDR_DQ22: U4.D20 U7.C2 | length 67.1
  Top Layer w0.12: U7.C2@32.44,7.92 32.83,8.31 33.913,8.31 ; 33.913,8.307 34.244,8.307 35.02,9.083 35.02,9.768 35.672,10.42 36.332,10.42 36.689,10.777 36.689,11.437 37.312,12.06 37.997,12.06 38.45,12.513 38.45,13.18 37.98,13.65 37.98,14.31 38.55,14.88 38.55,15.403 37.98,15.973 37.98,17.766 38.55,18.336 38.55,18.96 38.34,19.17 38.34,20.24 37.99,20.59 36.978,20.59 36.038,21.53 33.38,21.53 33.27,21.64 33.27,21.89 34.3,22.92 38.51,22.92 38.819,23.229 38.819,23.861 38.499,24.181 35.775,24.181 35.549,24.407 35.549,25.045 36.804,26.3 38.134,26.3 38.55,26.716 38.55,48.454 38.55,49.999 38.49,50.059 38.49,53.005 38.19,53.305 38.19,55.18 U4.D20@38.59,55.58
DDR_DQ23: U4.A21 U7.A7 | length 65.1
  Top Layer w0.12: U7.A7@28.44,6.32 28.996,6.32 29.24,6.076 29.24,5.9 28.92,5.58 28.92,5.4 29.329,4.99 29.77,4.99 29.97,4.79 34.836,4.79 36.615,6.569 36.615,6.817 36.896,7.098 37.108,7.098 37.299,7.289 37.299,7.501 37.478,7.68 37.726,7.68 41.75,11.704 41.75,13.31 41.64,13.42 41.64,13.61 41.75,13.72 41.75,16.489 41.5,16.739 41.5,16.896 41.75,17.146 41.75,19.934 41.625,20.059 41.625,20.275 41.75,20.401 41.75,23.459 41.66,23.549 41.66,24.21 41.75,24.3 41.75,26.859 41.429,27.18 41.429,27.47 41.7,27.741 41.7,29.154 41.307,29.547 41.307,29.723 41.75,30.166 41.75,31.314 41.61,31.454 41.61,31.627 41.75,31.767 41.75,33.299 41.28,33.769 41.28,34.307 41.75,34.777 41.75,36.196 41.28,36.666 41.28,37.234 41.71,37.664 41.71,38.206 41.28,38.636 41.28,39.291 41.75,39.761 41.75,40.924 41.59,41.084 41.59,41.226 41.75,41.386 41.75,42.609 41.589,42.77 41.589,42.911 41.75,43.071 41.75,44.529 41.29,44.989 41.29,45.164 41.72,45.594 41.72,45.74 41.28,46.18 41.28,46.651 41.75,47.121 41.75,48.504 41.494,48.76 41.494,48.956 41.735,49.196 41.735,50.675 40.99,51.42 40.99,53.061 41.31,53.381 41.31,54.17 40.99,54.49 U4.A21@40.99,54.78
DDR_DQ24: U4.V22 U7.E3 | length 66.9
  Top Layer w0.12: 23.424,49.11 20.04,49.11 17.77,46.84 17.77,43.715 16.835,42.78 16.835,37.009 17.92,35.924 17.92,35.16 21.12,31.96 21.12,27.932 25.962,23.09 30.422,23.09 32.822,20.69 35.632,20.69 37.14,19.182 37.14,13.076 33.995,9.931 ; 23.44,49.11 27.04,52.71 27.04,53.137 27.33,53.427 27.33,53.645 27.39,53.705 U4.V22@27.39,53.98 ; U7.E3@31.64,9.52 32.04,9.92 33.995,9.92
DDR_DQ25: U4.W20 U7.F2 | length 67
  Top Layer w0.12: U4.W20@26.59,55.58 26.96,55.21 26.96,53.58 26.62,53.24 26.62,52.937 26.196,52.513 26.196,52.476 23.25,49.53 19.866,49.53 17.35,47.014 17.35,43.889 16.415,42.954 16.415,36.835 17.5,35.75 17.5,34.986 20.7,31.786 20.7,27.758 25.788,22.67 30.248,22.67 32.648,20.27 35.458,20.27 36.72,19.008 36.72,13.34 34.08,10.7 ; U7.F2@32.44,10.32 32.82,10.7 34.08,10.7 ; 34.015,10.689 34.069,10.689 34.08,10.7
DDR_DQ26: U4.AB21 U7.F8 | length 65.2
  Top Layer w0.12: U4.AB21@24.19,54.78 22.984,54.78 22.704,54.5 20.887,54.5 13.63,47.243 13.63,34.244 16.63,31.244 16.63,28.94 16.335,28.645 15.305,28.645 14.95,28.29 14.95,25.77 15.74,24.98 19.617,24.98 24.667,19.93 29.078,19.93 29.52,19.498 29.52,13.554 29.63,13.444 29.63,12.3 29.011,11.681 29.011,11.139 28.632,10.76 28.341,10.76 27.901,10.32 U7.F8@27.64,10.32
DDR_DQ27: U4.AB20 U7.H8 | length 65.7
  Top Layer w0.12: U4.AB20@24.19,55.58 22.4,55.58 22.16,55.34 20.539,55.34 12.79,47.591 12.79,33.896 13.98,32.706 13.98,32.23 13.35,31.6 13.35,30.64 13.66,30.33 14.78,30.33 14.98,30.13 14.98,29.634 14.1,28.754 14.1,25.422 15.382,24.14 19.266,24.14 23.5,19.906 23.5,10.639 24.369,9.77 24.81,9.77 26.59,11.55 27.27,11.55 U7.H8@27.64,11.92
DDR_DQ28: U4.AA21 U7.F7 | length 65.5
  Top Layer w0.12: U4.AA21@24.99,54.78 24.57,54.36 23.395,54.36 23.115,54.08 21.061,54.08 14.05,47.069 14.05,34.418 17.05,31.418 17.05,29.476 17.826,28.7 18.1,28.7 18.208,28.592 18.208,28.272 17.936,28 16.73,28 16.18,27.45 16.18,25.86 16.64,25.4 19.791,25.4 24.831,20.36 29.291,20.36 29.95,19.701 29.95,13.76 30.07,13.64 30.07,11.38 29,10.31 28.99,10.32 U7.F7@28.44,10.32
DDR_DQ29: U4.AA20 U7.H7 | length 66.4
  Top Layer w0.12: 14.52,25.596 14.52,28.58 15.005,29.065 15.955,29.065 16.21,29.32 16.21,30.49 15.95,30.75 14.26,30.75 14.07,30.94 14.07,31.52 14.27,31.72 14.95,31.72 15.12,31.89 15.12,32.16 13.21,34.07 13.21,47.417 20.713,54.92 22.434,54.92 22.674,55.16 22.68,55.16 22.72,55.2 24.61,55.2 U4.AA20@24.99,55.58 ; 14.53,25.596 15.566,24.56 19.44,24.56 24.5,19.5 27.281,19.5 27.371,19.59 28.317,19.59 29.1,18.807 29.1,13.38 29.21,13.27 29.21,12.69 U7.H7@28.44,11.92
DDR_DQ30: U4.W22 U7.G2 | length 66.3
  Top Layer w0.12: U4.W22@26.59,53.98 26.59,53.733 26.26,53.403 26.26,53.171 23.039,49.95 19.622,49.95 16.78,47.108 16.78,46.67 16.54,46.43 16.29,46.43 16.13,46.27 16.13,45.83 16.31,45.65 16.67,45.65 16.78,45.54 16.78,43.913 15.995,43.128 15.995,36.661 17.08,35.576 17.08,35.3 16.865,35.085 16.69,35.085 16.49,34.885 16.49,34.651 16.691,34.45 17.442,34.45 20.28,31.612 20.28,27.584 25.614,22.25 30.074,22.25 32.474,19.85 35.284,19.85 36.3,18.834 36.3,13.564 34.221,11.485 33.045,11.485 32.88,11.32 32.88,11.27 32.73,11.12 U7.G2@32.44,11.12
DDR_DQ31: U4.W21 U7.H3 | length 67.1
  Top Layer w0.12: U4.W21@26.59,54.78 26.59,54.73 26.19,54.33 26.19,53.857 25.9,53.567 25.9,53.405 25.105,52.61 25.095,52.61 22.855,50.37 19.43,50.37 15.71,46.65 15.71,45.44 15.93,45.22 16.18,45.22 16.36,45.04 16.36,44.087 16.193,43.92 15.75,43.92 15.57,43.74 15.57,36.091 16.07,35.591 16.07,34.477 16.517,34.03 17.268,34.03 19.86,31.438 19.86,27.41 25.44,21.83 29.9,21.83 32.31,19.42 35.12,19.42 35.88,18.66 35.88,15.22 35.72,15.06 34.931,15.06 33.9,14.029 33.9,12.751 33.494,12.345 33.034,12.345 32.85,12.161 32.85,11.816 32.549,11.515 32.336,11.515 32.08,11.771 32.08,11.79 31.95,11.92 U7.H3@31.64,11.92
DDR_DQM0: U4.G20 U6.D3 | length 46
  Top Layer w0.12: U6.D3@29.39,28.58 28.08,28.58 27.85,28.35 27.85,28.011 29.03,26.831 29.03,26.031 29.241,25.82 31.65,25.82 32.461,26.631 32.461,27.397 33.729,28.664 33.729,29.591 34.66,30.522 34.66,31.362 34.84,31.542 34.84,34.828 35.39,35.378 35.39,44.98 35.29,45.08 34.785,45.08 34.325,45.54 31.445,45.54 31.04,45.945 31.04,46.814 31.516,47.29 34.286,47.29 35.74,48.744 35.74,55.13 U4.G20@36.19,55.58 ; U6.D3@29.41,28.577 U6.D3@29.433,28.6
DDR_DQM1: U4.T21 U6.E7 | length 46.1
  Top Layer w0.1: 28.7,53.8 28.7,53.811
  Top Layer w0.12: U6.E7@26.19,29.38 26.64,29.38 27.84,30.58 27.84,39.315 26.17,40.985 21.88,40.985 20.65,39.755 20.65,38.32 20.18,37.85 19.35,37.85 18.935,38.265 18.935,41.91 19.87,42.845 19.87,45.97 20.88,46.98 24.969,46.98 28.71,50.721 28.71,51.92 28.84,52.04 28.84,53.43 28.703,53.567 28.703,53.815 28.67,53.847 ; 28.696,53.821 28.67,53.847 ; U4.T21@28.99,54.78 28.99,54.433 28.67,54.112 28.67,53.847
DDR_DQM2: U4.C22 U7.D3 | length 65.6
  Top Layer w0.12: U7.D3@31.59,8.72 30.74,9.57 30.05,9.57 29.7,9.22 29.7,8.61 30.795,7.515 30.795,6.521 31.356,5.96 33.89,5.96 35.145,7.215 35.145,7.426 36.28,8.561 36.28,9.05 36.39,9.16 37.09,9.16 37.74,9.81 37.74,10.046 37.949,10.255 37.949,10.669 38.07,10.79 38.72,10.79 38.945,11.015 38.945,11.226 40.123,12.404 40.123,12.842 39.81,13.155 39.81,13.902 40.19,14.282 40.19,15.545 39.25,16.485 39.25,17.254 40.19,18.194 40.19,19.102 39.6,19.692 39.6,20.585 39.967,20.953 39.967,21.197 39.875,21.29 39.27,21.29 39.106,21.454 39.106,21.66 39.415,21.969 39.833,21.969 40.19,22.326 40.19,26.024 39.81,26.404 39.81,26.73 39.81,28.09 40.14,28.42 40.14,28.635 39.81,28.965 39.81,30.456 40.1,30.746 40.1,31.42 39.824,31.696 39.824,31.92 40.14,32.236 40.14,32.794 39.81,33.124 39.81,34.916 40.14,35.246 40.14,35.727 39.81,36.057 39.81,40.54 39.81,41.55 40.14,41.88 40.14,42.12 39.81,42.45 39.81,43.21 40.14,43.54 40.14,44.034 39.81,44.364 39.81,47.224 39.81,47.26 40.14,47.59 40.14,48.035 39.81,48.365 39.81,49.365 40.14,49.695 40.14,50.191 39.61,50.721 39.61,53.54 39.39,53.76 U4.C22@39.39,53.98
DDR_DQM3: U4.AA22 U7.E7 | length 64.7
  Top Layer w0.12: U4.AA22@24.99,53.98 24.63,53.62 23.541,53.62 23.501,53.66 21.235,53.66 14.47,46.895 14.47,34.592 17.47,31.592 17.47,29.65 18,29.12 18.33,29.12 18.65,28.8 18.65,28.12 18.11,27.58 17.435,27.58 16.92,27.065 16.92,26.36 17.46,25.82 19.965,25.82 25.005,20.78 29.465,20.78 30.37,19.875 30.37,19.665 30.43,19.605 30.43,10.96 28.99,9.52 U7.E7@28.44,9.52
DDR_DQS0_N: TP21.1 U4.G21 U6.B7 | length 46.4
  Top Layer w0.1: U6.B7@26.19,26.98 26.47,27.26 27.605,27.26 28.39,26.475 28.39,25.4 28.61,25.18 31.915,25.18 33.101,26.366 33.101,27.131 34.369,28.399 34.369,29.326 35.457,30.413 TP21.1@35.48,30.437 ; TP21.1@35.553,30.33 35.553,30.364 TP21.1@35.48,30.437 ; U4.G21@36.19,54.78 36.19,54.418 36.5,54.108 36.5,53.852 36.42,53.772 36.42,52.734 36.32,52.634 36.32,48.359 34.611,46.65 31.781,46.65 31.68,46.549 31.68,46.32 31.82,46.18 34.59,46.18 35.05,45.72 35.795,45.72 36.03,45.485 36.03,35.113 35.48,34.563 TP21.1@35.48,30.437
DDR_DQS0_P: TP20.1 U4.G22 U6.C7 | length 45.1
  Top Layer w0.1: U6.C7@26.19,27.78 26.48,27.49 27.7,27.49 28.62,26.57 28.62,25.495 28.705,25.41 31.82,25.41 32.871,26.462 32.871,27.227 34.139,28.494 34.139,29.421 35.244,30.526 TP20.1@35.25,30.532 ; TP20.1@35.14,30.58 35.202,30.58 TP20.1@35.25,30.532 ; 36.177,52.817 36.09,52.729 36.09,48.454 34.516,46.88 31.686,46.88 31.45,46.644 31.45,46.225 31.725,45.95 34.495,45.95 34.955,45.49 35.7,45.49 35.8,45.39 35.8,35.208 35.25,34.658 35.25,30.63 TP20.1@35.25,30.532 ; 36.19,52.829 U4.G22@36.19,53.98
DDR_DQS1_N: U4.R22 U6.G3 | length 44.9
  Top Layer w0.1: U6.G3@29.39,30.98 29.11,30.7 28.833,30.7 28.34,31.193 28.34,34.325 28.61,34.595 28.61,39.533 26.518,41.625 21.615,41.625 20.01,40.02 20.01,38.585 19.915,38.49 19.615,38.49 19.575,38.53 19.575,41.645 20.51,42.58 20.51,45.705 21.125,46.32 26.84,46.32 27.27,46.75 27.27,48.376 29.35,50.456 29.35,51.3 29.545,51.495 29.545,53.735 29.553,53.743 29.565,53.755 U4.R22@29.79,53.98
DDR_DQS1_P: U4.T22 U6.F3 | length 45.3
  Top Layer w0.1: 28.37,34.69 28.38,34.7 28.38,39.438 26.549,41.269 26.423,41.395 21.71,41.395 20.24,39.925 20.24,38.49 20.01,38.26 19.52,38.26 19.345,38.435 19.345,41.74 20.28,42.675 20.28,45.8 21.03,46.55 26.745,46.55 27.04,46.845 27.04,48.471 29.12,50.551 29.12,51.395 29.315,51.59 29.315,53.655 U4.T22@28.99,53.98 ; 28.375,34.685 28.11,34.42 28.11,31.097 28.737,30.47 29.1,30.47 U6.F3@29.39,30.18
DDR_DQS2_N: TP27.1 U4.B22 U7.B7 | length 66.1
  Top Layer w0.1: U7.B7@28.44,7.12 28.72,7.4 30.005,7.4 30.155,7.25 30.155,5.835 30.57,5.42 34.292,5.42 35.785,6.913 35.785,7.161 37.144,8.52 37.355,8.52 38.38,9.545 38.38,9.715 38.815,10.15 38.985,10.15 39.585,10.75 39.585,10.961 39.804,11.18 40.015,11.18 40.92,12.085 40.92,12.95 40.46,13.41 40.46,13.647 40.92,14.107 40.92,14.685 40.83,14.775 40.83,15.525 40.92,15.615 40.92,16.145 40.595,16.47 40.44,16.47 40.17,16.47 39.89,16.75 39.89,16.989 40.041,17.14 40.57,17.14 40.92,17.49 40.92,19.59 40.65,19.86 40.337,19.86 40.24,19.957 40.24,20.32 40.38,20.46 40.635,20.46 40.92,20.745 40.92,21.15 40.49,21.58 40.49,21.721 40.92,22.151 40.92,23.115 40.83,23.205 40.83,24.554 40.92,24.644 40.92,26.515 40.625,26.81 40.515,26.81 40.45,26.875 40.45,27.825 40.49,27.865 40.65,27.865 40.87,28.085 40.87,28.81 40.455,29.225 40.455,30.045 40.92,30.51 40.92,30.905 40.74,31.085 40.74,31.931 40.92,32.111 40.92,32.955 40.45,33.425 40.45,34.651 40.92,35.121 40.92,35.852 40.45,36.322 40.45,38.4 40.45,39.635 40.92,40.105 40.92,40.58 40.45,41.05 40.45,41.26 40.92,41.73 40.92,42.265 40.45,42.735 40.45,42.945 40.92,43.415 40.92,44.185 40.45,44.655 40.45,46.995 40.92,47.465 40.92,48.16 40.45,48.63 40.45,49.1 40.905,49.555 40.905,50.331 40.19,51.046 U4.B22@40.19,53.98
DDR_DQS2_P: TP28.1 U4.C21 U7.C7 | length 66.8
  Top Layer w0.1: U7.C7@28.44,7.92 28.73,7.63 30.1,7.63 30.385,7.345 30.385,5.93 30.665,5.65 34.197,5.65 35.555,7.008 35.555,7.256 37.049,8.75 37.26,8.75 38.15,9.64 38.15,9.81 38.72,10.38 38.89,10.38 39.355,10.845 39.355,11.056 39.709,11.41 39.92,11.41 40.69,12.18 40.69,12.855 40.23,13.315 40.23,13.742 40.69,14.202 40.69,14.59 40.6,14.68 40.6,15.62 40.69,15.71 40.69,16.05 40.54,16.2 40.5,16.24 40.44,16.24 40.075,16.24 39.66,16.655 39.66,17.084 39.946,17.37 40.475,17.37 40.69,17.585 40.69,19.495 40.555,19.63 40.242,19.63 40.01,19.862 40.01,20.415 40.285,20.69 40.54,20.69 40.69,20.84 40.69,21.055 40.26,21.485 40.26,21.816 40.69,22.246 40.69,23.02 40.6,23.11 40.6,24.649 40.69,24.739 40.69,26.42 40.53,26.58 40.42,26.58 40.22,26.78 40.22,27.92 40.395,28.095 40.555,28.095 40.64,28.18 40.64,28.715 40.225,29.13 40.225,30.14 40.69,30.605 40.69,30.81 40.51,30.99 40.51,32.026 40.69,32.206 40.69,32.86 40.22,33.33 40.22,34.746 40.69,35.216 40.69,35.757 40.22,36.227 40.22,37.805 40.22,39.73 40.69,40.2 40.69,40.485 40.22,40.955 40.22,41.355 40.69,41.825 40.69,42.17 40.22,42.64 40.22,43.04 40.69,43.51 40.69,44.09 40.22,44.56 40.22,47.09 40.69,47.56 40.69,48.065 40.22,48.535 40.22,49.195 40.675,49.65 40.675,50.236 39.96,50.951 39.96,53.75 39.85,53.86 39.85,54.029 39.39,54.489 U4.C21@39.39,54.78
DDR_DQS3_N: U4.Y22 U7.G3 | length 66.3
  Top Layer w0.1: U4.Y22@25.761,54.008 25.55,53.797 25.55,53.635 24.935,53.02 24.925,53.02 22.685,50.78 19.26,50.78 15.16,46.68 15.16,45.2 15.5,44.86 15.5,44.41 15.16,44.07 15.16,34.807 16.347,33.62 17.098,33.62 17.62,33.098 17.62,32.47 17.808,32.282 18.437,32.282 19.45,31.268 19.45,30.71 18.98,30.24 18.265,30.24 18.11,30.085 18.11,29.915 18.265,29.76 18.95,29.76 19.45,29.26 19.45,27.54 18.85,26.94 17.7,26.94 17.56,26.8 17.56,26.625 17.725,26.46 20.23,26.46 25.27,21.42 29.731,21.42 31.01,20.14 31.01,14.185 30.89,14.065 30.89,11.09 31.15,10.83 31.35,10.83 U7.G3@31.64,11.12
DDR_DQS3_P: U4.Y21 U7.F3 | length 67.5
  Top Layer w0.1: U4.Y21@25.79,54.78 25.78,54.77 25.78,54.41 25.32,53.95 25.32,53.73 24.84,53.25 24.83,53.25 22.59,51.01 19.165,51.01 14.92,46.765 14.92,45.115 15.27,44.765 15.27,44.505 14.93,44.165 14.93,34.712 16.252,33.39 17.003,33.39 17.39,33.003 17.39,32.375 17.713,32.052 18.342,32.052 19.22,31.173 19.22,30.805 18.885,30.47 18.17,30.47 17.88,30.18 17.88,29.82 18.17,29.53 18.855,29.53 19.22,29.165 19.22,27.635 18.755,27.17 17.605,27.17 17.33,26.895 17.33,26.53 17.63,26.23 20.135,26.23 25.175,21.19 29.635,21.19 30.78,20.045 30.78,14.28 30.66,14.16 30.66,10.995 31.055,10.6 31.36,10.6 U7.F3@31.64,10.32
